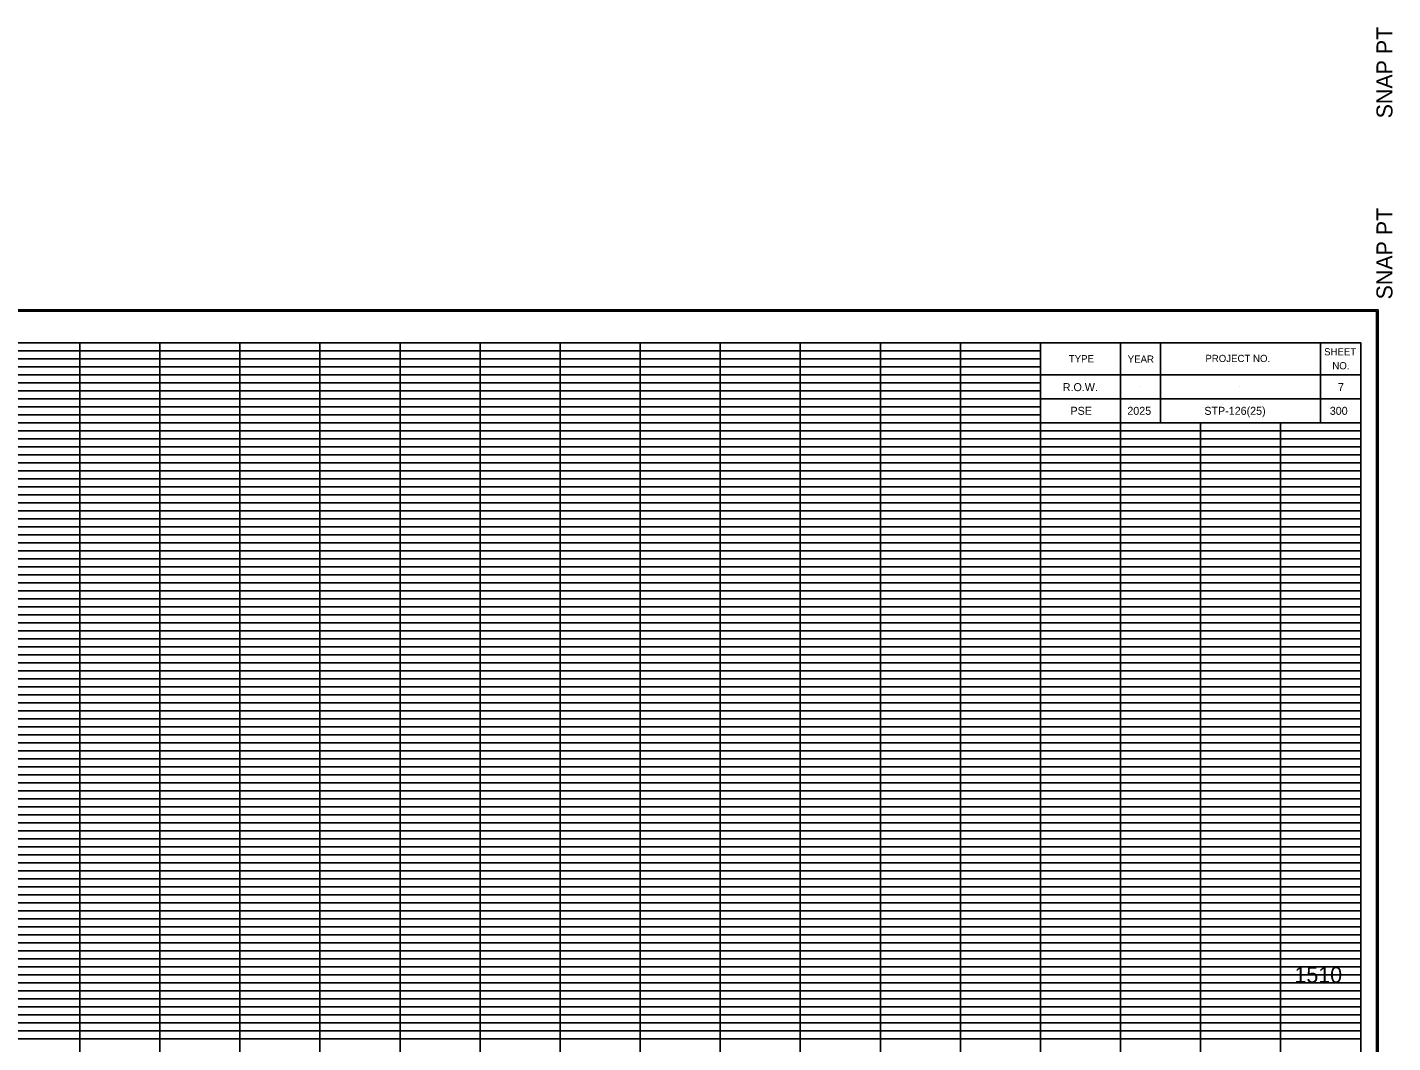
# Model space of a CAD drawing. Extents: x 980 to 2064, y 978 to 2267.
# Drawn here: x 1523.4 to 1694, y 1382.5 to 1509.4 of the extents above; entities that cross this region are included whole.
import ezdxf

# ---------------------------------------------------------------- set-up
doc = ezdxf.new("R2010")
doc.units = 0
for name, color, linetype in [('Default', 7, 'Continuous'), ('DESIGN - SCRATCH - User 1', 7, 'Continuous'), ('DESIGN - SHEET - Corner Text', 7, 'Continuous'), ('DESIGN - SHEET - Light Grid', 7, 'Continuous'), ('DESIGN - SHEET - Linework', 7, 'Continuous'), ('DESIGN - SHEET - Plot Shape', 7, 'Continuous')]:
    doc.layers.add(name, color=color, linetype=linetype)

# ---------------------------------------------------------------- blocks, each defined once
blk = doc.blocks.new('XSTSHT')
at = {"layer": 'DESIGN - SHEET - Corner Text'}
blk.add_text('SNAP PT  ', height=0.2, rotation=90, dxfattribs=at).set_placement((32.397, -2.194))

msp = doc.modelspace()

# ---------------------------------------------------------------- linework, layer by layer
at = {"layer": 'DESIGN - SCRATCH - User 1'}
for p, q in [((1655, 1464.5), (1655, 1464.5)), ((1662.4, 1464.5), (1662.4, 1464.5)), ((1674.9, 1464.5), (1674.9, 1464.5)), ((1687.4, 1464.5), (1687.4, 1464.5)), ((1655, 1461.5), (1655, 1461.5)), ((1662.4, 1461.5), (1662.4, 1461.5)), ((1674.9, 1461.5), (1674.9, 1461.5)), ((1687.4, 1461.5), (1687.4, 1461.5))]:
    msp.add_line(p, q, dxfattribs=at)
at = {"layer": 'DESIGN - SHEET - Light Grid'}
for p, q in [((1450, 1469), (1530, 1469)), ((1530, 1469), (1610, 1469)), ((1610, 1469), (1650, 1469)), ((1450, 1468), (1530, 1468)), ((1450, 1467), (1530, 1467)), ((1530, 1468), (1610, 1468)), ((1530, 1467), (1610, 1467)), ((1610, 1468), (1650, 1468)), ((1610, 1467), (1650, 1467)), ((1450, 1466), (1530, 1466)), ((1530, 1466), (1610, 1466)), ((1610, 1466), (1650, 1466)), ((1450, 1465), (1530, 1465)), ((1450, 1464), (1530, 1464)), ((1530, 1465), (1610, 1465)), ((1530, 1464), (1610, 1464)), ((1610, 1465), (1650, 1465)), ((1610, 1464), (1650, 1464)), ((1450, 1463), (1530, 1463)), ((1450, 1462), (1530, 1462)), ((1530, 1463), (1610, 1463)), ((1530, 1462), (1610, 1462)), ((1610, 1463), (1650, 1463)), ((1610, 1462), (1650, 1462)), ((1450, 1461), (1530, 1461)), ((1530, 1461), (1610, 1461)), ((1610, 1461), (1650, 1461)), ((1450, 1459), (1530, 1459)), ((1530, 1459), (1610, 1459)), ((1610, 1459), (1690, 1459)), ((1450, 1458), (1530, 1458)), ((1450, 1457), (1530, 1457)), ((1530, 1458), (1610, 1458)), ((1530, 1457), (1610, 1457)), ((1610, 1458), (1690, 1458)), ((1610, 1457), (1690, 1457)), ((1450, 1456), (1530, 1456)), ((1450, 1455), (1530, 1455)), ((1530, 1456), (1610, 1456)), ((1530, 1455), (1610, 1455)), ((1610, 1456), (1690, 1456)), ((1610, 1455), (1690, 1455)), ((1450, 1454), (1530, 1454)), ((1530, 1454), (1610, 1454)), ((1610, 1454), (1690, 1454)), ((1450, 1453), (1530, 1453)), ((1450, 1452), (1530, 1452)), ((1530, 1453), (1610, 1453)), ((1530, 1452), (1610, 1452)), ((1610, 1453), (1690, 1453)), ((1610, 1452), (1690, 1452)), ((1450, 1451), (1530, 1451)), ((1530, 1451), (1610, 1451)), ((1610, 1451), (1690, 1451)), ((1450, 1449), (1530, 1449)), ((1530, 1449), (1610, 1449)), ((1610, 1449), (1690, 1449)), ((1450, 1448), (1530, 1448)), ((1450, 1447), (1530, 1447)), ((1530, 1448), (1610, 1448)), ((1530, 1447), (1610, 1447)), ((1610, 1448), (1690, 1448)), ((1610, 1447), (1690, 1447)), ((1450, 1446), (1530, 1446)), ((1450, 1445), (1530, 1445)), ((1530, 1446), (1610, 1446)), ((1530, 1445), (1610, 1445)), ((1610, 1446), (1690, 1446)), ((1610, 1445), (1690, 1445)), ((1450, 1444), (1530, 1444)), ((1450, 1443), (1530, 1443)), ((1530, 1444), (1610, 1444)), ((1530, 1443), (1610, 1443)), ((1610, 1444), (1690, 1444)), ((1610, 1443), (1690, 1443)), ((1450, 1442), (1530, 1442)), ((1530, 1442), (1610, 1442)), ((1610, 1442), (1690, 1442)), ((1450, 1441), (1530, 1441)), ((1530, 1441), (1610, 1441)), ((1610, 1441), (1690, 1441)), ((1450, 1439), (1530, 1439)), ((1450, 1438), (1530, 1438)), ((1530, 1439), (1610, 1439)), ((1530, 1438), (1610, 1438)), ((1610, 1439), (1690, 1439)), ((1610, 1438), (1690, 1438)), ((1450, 1437), (1530, 1437)), ((1530, 1437), (1610, 1437)), ((1610, 1437), (1690, 1437)), ((1450, 1436), (1530, 1436)), ((1450, 1435), (1530, 1435)), ((1530, 1436), (1610, 1436)), ((1530, 1435), (1610, 1435)), ((1610, 1436), (1690, 1436)), ((1610, 1435), (1690, 1435)), ((1450, 1434), (1530, 1434)), ((1450, 1433), (1530, 1433)), ((1530, 1434), (1610, 1434)), ((1530, 1433), (1610, 1433)), ((1610, 1434), (1690, 1434)), ((1610, 1433), (1690, 1433)), ((1450, 1432), (1530, 1432)), ((1450, 1431), (1530, 1431)), ((1530, 1432), (1610, 1432)), ((1530, 1431), (1610, 1431)), ((1610, 1432), (1690, 1432)), ((1610, 1431), (1690, 1431)), ((1450, 1429), (1530, 1429)), ((1450, 1428), (1530, 1428)), ((1530, 1429), (1610, 1429)), ((1530, 1428), (1610, 1428)), ((1610, 1429), (1690, 1429)), ((1610, 1428), (1690, 1428)), ((1450, 1427), (1530, 1427)), ((1450, 1426), (1530, 1426)), ((1530, 1427), (1610, 1427)), ((1530, 1426), (1610, 1426)), ((1610, 1427), (1690, 1427)), ((1610, 1426), (1690, 1426)), ((1450, 1425), (1530, 1425)), ((1530, 1425), (1610, 1425)), ((1610, 1425), (1690, 1425)), ((1450, 1424), (1530, 1424)), ((1450, 1423), (1530, 1423)), ((1530, 1424), (1610, 1424)), ((1530, 1423), (1610, 1423)), ((1610, 1424), (1690, 1424)), ((1610, 1423), (1690, 1423)), ((1450, 1422), (1530, 1422)), ((1450, 1421), (1530, 1421)), ((1530, 1422), (1610, 1422)), ((1530, 1421), (1610, 1421)), ((1610, 1422), (1690, 1422)), ((1610, 1421), (1690, 1421)), ((1450, 1419), (1530, 1419)), ((1450, 1418), (1530, 1418)), ((1530, 1419), (1610, 1419)), ((1530, 1418), (1610, 1418)), ((1610, 1419), (1690, 1419)), ((1610, 1418), (1690, 1418)), ((1450, 1417), (1530, 1417)), ((1450, 1416), (1530, 1416)), ((1530, 1417), (1610, 1417)), ((1530, 1416), (1610, 1416)), ((1610, 1417), (1690, 1417)), ((1610, 1416), (1690, 1416)), ((1450, 1415), (1530, 1415)), ((1450, 1414), (1530, 1414)), ((1530, 1415), (1610, 1415)), ((1530, 1414), (1610, 1414)), ((1610, 1415), (1690, 1415)), ((1610, 1414), (1690, 1414)), ((1450, 1413), (1530, 1413)), ((1530, 1413), (1610, 1413)), ((1610, 1413), (1690, 1413)), ((1450, 1412), (1530, 1412)), ((1450, 1411), (1530, 1411)), ((1530, 1412), (1610, 1412)), ((1530, 1411), (1610, 1411)), ((1610, 1412), (1690, 1412)), ((1610, 1411), (1690, 1411)), ((1450, 1409), (1530, 1409)), ((1530, 1409), (1610, 1409)), ((1610, 1409), (1690, 1409)), ((1450, 1408), (1530, 1408)), ((1530, 1408), (1610, 1408)), ((1610, 1408), (1690, 1408)), ((1450, 1407), (1530, 1407)), ((1450, 1406), (1530, 1406)), ((1530, 1407), (1610, 1407)), ((1530, 1406), (1610, 1406)), ((1610, 1407), (1690, 1407)), ((1610, 1406), (1690, 1406)), ((1450, 1405), (1530, 1405)), ((1450, 1404), (1530, 1404)), ((1530, 1405), (1610, 1405)), ((1530, 1404), (1610, 1404)), ((1610, 1405), (1690, 1405)), ((1610, 1404), (1690, 1404)), ((1450, 1403), (1530, 1403)), ((1450, 1402), (1530, 1402)), ((1530, 1403), (1610, 1403)), ((1530, 1402), (1610, 1402)), ((1610, 1403), (1690, 1403)), ((1610, 1402), (1690, 1402)), ((1450, 1401), (1530, 1401)), ((1530, 1401), (1610, 1401)), ((1610, 1401), (1690, 1401)), ((1450, 1399), (1530, 1399)), ((1530, 1399), (1610, 1399)), ((1610, 1399), (1690, 1399)), ((1450, 1398), (1530, 1398)), ((1450, 1397), (1530, 1397)), ((1530, 1398), (1610, 1398)), ((1530, 1397), (1610, 1397)), ((1610, 1398), (1690, 1398)), ((1610, 1397), (1690, 1397)), ((1450, 1396), (1530, 1396)), ((1530, 1396), (1610, 1396)), ((1610, 1396), (1690, 1396)), ((1450, 1395), (1530, 1395)), ((1450, 1394), (1530, 1394)), ((1530, 1395), (1610, 1395)), ((1530, 1394), (1610, 1394)), ((1610, 1395), (1690, 1395)), ((1610, 1394), (1690, 1394)), ((1450, 1393), (1530, 1393)), ((1450, 1392), (1530, 1392)), ((1530, 1393), (1610, 1393)), ((1530, 1392), (1610, 1392)), ((1610, 1393), (1690, 1393)), ((1610, 1392), (1690, 1392)), ((1450, 1391), (1530, 1391)), ((1530, 1391), (1610, 1391)), ((1610, 1391), (1690, 1391)), ((1450, 1389), (1530, 1389)), ((1530, 1389), (1610, 1389)), ((1610, 1389), (1690, 1389)), ((1450, 1388), (1530, 1388)), ((1450, 1387), (1530, 1387)), ((1530, 1388), (1610, 1388)), ((1530, 1387), (1610, 1387)), ((1610, 1388), (1690, 1388)), ((1610, 1387), (1690, 1387)), ((1450, 1386), (1530, 1386)), ((1450, 1385), (1530, 1385)), ((1530, 1386), (1610, 1386)), ((1530, 1385), (1610, 1385)), ((1610, 1386), (1690, 1386)), ((1610, 1385), (1690, 1385)), ((1450, 1384), (1530, 1384)), ((1530, 1384), (1610, 1384)), ((1610, 1384), (1690, 1384)), ((1450, 1383), (1530, 1383)), ((1530, 1383), (1610, 1383)), ((1610, 1383), (1690, 1383))]:
    msp.add_line(p, q, dxfattribs=at)
at = {"layer": 'DESIGN - SHEET - Linework'}
for p, q in [((1351.77, 1474.14), (1692.17, 1474.14)), ((1692.17, 1474.14), (1692.17, 1255.86)), ((1530, 1260), (1530, 1470)), ((1540, 1260), (1540, 1470)), ((1550, 1260), (1550, 1470)), ((1560, 1260), (1560, 1470)), ((1570, 1260), (1570, 1470)), ((1580, 1260), (1580, 1470)), ((1590, 1260), (1590, 1470)), ((1600, 1260), (1600, 1470)), ((1610, 1260), (1610, 1470)), ((1620, 1260), (1620, 1470)), ((1630, 1260), (1630, 1470)), ((1640, 1260), (1640, 1470)), ((1370, 1460), (1650, 1460)), ((1650, 1260), (1650, 1460)), ((1660, 1260), (1660, 1460)), ((1670, 1260), (1670, 1460)), ((1680, 1260), (1680, 1460)), ((1370, 1450), (1690, 1450)), ((1370, 1440), (1690, 1440)), ((1370, 1430), (1690, 1430)), ((1370, 1420), (1690, 1420)), ((1370, 1410), (1690, 1410)), ((1370, 1400), (1690, 1400)), ((1370, 1390), (1690, 1390))]:
    msp.add_line(p, q, dxfattribs=at)
for points in [[(1370, 1470), (1370, 1260), (1690, 1260), (1690, 1470), (1370, 1470)], [(1650, 1470), (1650, 1460), (1690, 1460), (1690, 1470), (1685, 1470), (1685, 1460), (1665, 1460), (1665, 1470), (1660, 1470), (1660, 1460), (1690, 1460), (1650, 1460), (1650, 1463), (1690, 1463), (1690, 1466), (1650, 1466)]]:
    msp.add_lwpolyline(points, dxfattribs=at)
at = {"layer": 'DESIGN - SHEET - Plot Shape'}
for points in [[(1351.97, 1473.94), (1691.97, 1473.94), (1691.97, 1256.06), (1351.97, 1256.06)], [(1361.5, 1470), (1690, 1470), (1690, 1257.5), (1361.5, 1257.5)]]:
    msp.add_lwpolyline(points, close=True, dxfattribs=at)

# ---------------------------------------------------------------- block references
at = {"layer": 'Default', "xscale": 10, "yscale": 10}
msp.add_blockref('XSTSHT', (1370, 1520), dxfattribs=at)

# ---------------------------------------------------------------- texts
at = {"layer": 'Default'}
msp.add_text('     1510     ', height=2, dxfattribs=at).set_placement((1678.01, 1390))
at = {"layer": 'DESIGN - SHEET - Corner Text'}
msp.add_text('  SNAP PT', height=2, rotation=90, dxfattribs=at).set_placement((1693.97, 1473.94))
for s, height, p in [('PROJECT NO.', 0.9, (1670.6, 1467.6)), ('SHEET', 0.9, (1685.43, 1468.43)), ('TYPE', 0.9, (1653.54, 1467.56)), ('YEAR', 0.9, (1660.9, 1467.52)), ('NO.', 0.9, (1686.46, 1466.69)), ('R.O.W.', 1, (1652.79, 1463.96)), ('7', 1, (1687.16, 1463.96)), ('PSE', 1, (1653.75, 1461)), ('2025', 1, (1660.85, 1461)), ('STP-126(25)', 1, (1670.47, 1461)), ('300', 1, (1686.14, 1461))]:
    msp.add_text(s, height=height, dxfattribs=at).set_placement(p)

doc.saveas('drawing.dxf')
